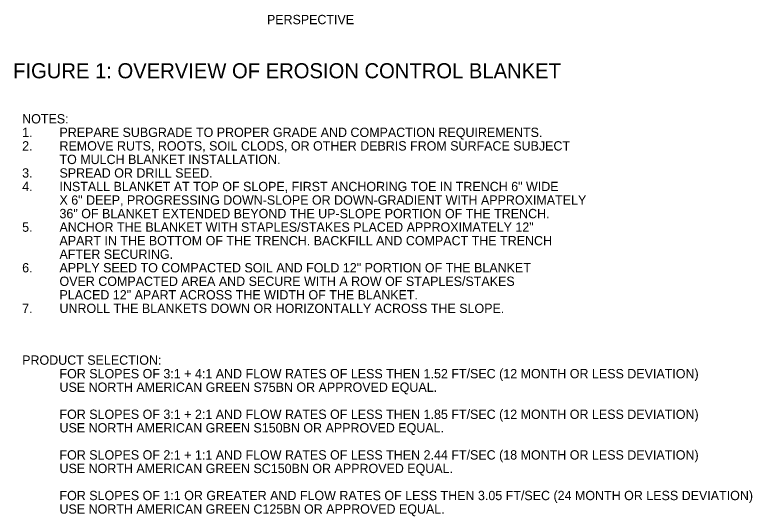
# Model space of a CAD drawing. Extents: x 27123946 to 27124151, y 1145898 to 1146027.
# Drawn here: x 27123952.1 to 27124017.6, y 1145916.5 to 1145961 of the extents above; entities that cross this region are included whole.
import ezdxf

# ---------------------------------------------------------------- set-up
doc = ezdxf.new("R2010")
doc.units = 0
doc.layers.add('G-ANNO-TEXT', color=7, linetype='Continuous')

msp = doc.modelspace()

# ---------------------------------------------------------------- texts
at = {"layer": 'G-ANNO-TEXT'}
for s, height, p in [('PERSPECTIVE', 0.82569, (27123974.498, 1145960.191)), ('FIGURE 1: OVERVIEW OF EROSION CONTROL BLANKET', 1.34175, (27123951.952, 1145955.381)), ('NOTES:', 0.828, (27123952.759, 1145951.37)), ('1.', 0.828, (27123952.759, 1145950.167)), ('PREPARE SUBGRADE TO PROPER GRADE AND COMPACTION REQUIREMENTS.', 0.828, (27123956.071, 1145950.167)), ('2.', 0.828, (27123952.759, 1145948.964)), ('REMOVE RUTS, ROOTS, SOIL CLODS, OR OTHER DEBRIS FROM SURFACE SUBJECT', 0.828, (27123956.071, 1145948.964)), ('TO MULCH BLANKET INSTALLATION.', 0.828, (27123956.071, 1145947.761)), ('3.', 0.828, (27123952.759, 1145946.558)), ('SPREAD OR DRILL SEED.', 0.828, (27123956.071, 1145946.558)), ('4.', 0.828, (27123952.759, 1145945.355)), ('INSTALL BLANKET AT TOP OF SLOPE, FIRST ANCHORING TOE IN TRENCH 6" WIDE', 0.828, (27123956.071, 1145945.355)), ('X 6" DEEP, PROGRESSING DOWN-SLOPE OR DOWN-GRADIENT WITH APPROXIMATELY', 0.828, (27123956.071, 1145944.152)), ('36" OF BLANKET EXTENDED BEYOND THE UP-SLOPE PORTION OF THE TRENCH.', 0.828, (27123956.071, 1145942.949)), ('5.', 0.828, (27123952.759, 1145941.746)), ('ANCHOR THE BLANKET WITH STAPLES/STAKES PLACED APPROXIMATELY 12"', 0.828, (27123956.071, 1145941.746)), ('APART IN THE BOTTOM OF THE TRENCH. BACKFILL AND COMPACT THE TRENCH', 0.828, (27123956.071, 1145940.543)), ('AFTER SECURING.', 0.828, (27123956.071, 1145939.34)), ('6.', 0.828, (27123952.759, 1145938.137)), ('APPLY SEED TO COMPACTED SOIL AND FOLD 12" PORTION OF THE BLANKET', 0.828, (27123956.071, 1145938.137)), ('OVER COMPACTED AREA AND SECURE WITH A ROW OF STAPLES/STAKES', 0.828, (27123956.071, 1145936.934)), ('PLACED 12" APART ACROSS THE WIDTH OF THE BLANKET.', 0.828, (27123956.071, 1145935.731)), ('7.', 0.828, (27123952.759, 1145934.528)), ('UNROLL THE BLANKETS DOWN OR HORIZONTALLY ACROSS THE SLOPE.', 0.828, (27123956.071, 1145934.528)), ('PRODUCT SELECTION:', 0.828, (27123952.759, 1145929.929)), ('FOR SLOPES OF 3:1 + 4:1 AND FLOW RATES OF LESS THEN 1.52 FT/SEC (12 MONTH OR LESS DEVIATION)', 0.828, (27123956.071, 1145928.726)), ('USE NORTH AMERICAN GREEN S75BN OR APPROVED EQUAL.', 0.828, (27123956.071, 1145927.523)), ('FOR SLOPES OF 3:1 + 2:1 AND FLOW RATES OF LESS THEN 1.85 FT/SEC (12 MONTH OR LESS DEVIATION)', 0.828, (27123956.071, 1145925.117)), ('USE NORTH AMERICAN GREEN S150BN OR APPROVED EQUAL. ', 0.828, (27123956.071, 1145923.914)), ('FOR SLOPES OF 2:1 + 1:1 AND FLOW RATES OF LESS THEN 2.44 FT/SEC (18 MONTH OR LESS DEVIATION)', 0.828, (27123956.071, 1145921.508)), ('USE NORTH AMERICAN GREEN SC150BN OR APPROVED EQUAL. ', 0.828, (27123956.071, 1145920.305)), ('FOR SLOPES OF 1:1 OR GREATER AND FLOW RATES OF LESS THEN 3.05 FT/SEC (24 MONTH OR LESS DEVIATION)', 0.828, (27123956.071, 1145917.899)), ('USE NORTH AMERICAN GREEN C125BN OR APPROVED EQUAL. ', 0.828, (27123956.071, 1145916.696))]:
    msp.add_text(s, height=height, dxfattribs=at).set_placement(p)

doc.saveas('drawing.dxf')
